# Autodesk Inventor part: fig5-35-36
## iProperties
Shininess: 77.0
Angle Display Precision: 2
Document Length Units: 11269
Document Angle Units: 11279
Document Time Units: 11290
Document Mass Units: 11283
Document Length Units Precision: 3
Document Angle Units Precision: 2
Created: 2001-12
Part Number: fig5-35-36
Document SubType Name: Modeling
Designer: Renu Muthoo
Density: 0.0
Volumn: 0.0
Area: 0.0
PropertySet Name: Model Information
Control State: 0
Master: False
Checked Out: False
Author: Renu Muthoo
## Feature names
1. Extrusion1
2. Extrusion3
3. Chamfer4
